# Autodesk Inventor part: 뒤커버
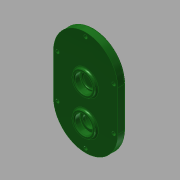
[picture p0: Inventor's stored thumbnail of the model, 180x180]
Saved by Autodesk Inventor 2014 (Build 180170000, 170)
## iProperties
Created: 2016-12
Part Number: 뒤커버
Material: 일반
Document SubType Name: Modeling
Designer: mduedu
Density: 1 g/cm^3
Appearance: 매끄러움 - 짙은 산림 녹색
Mass: 87.2434 g
Surface Area: 240.701 cm^2
Volume: 87.2434 cm^3
Author: mduedu
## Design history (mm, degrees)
sketch "스케치1"
  geometry: L1 (40, -25)-(40, 25); L2 (-40, 25)-(-40, -25); L3 (-40, -25)-(40, 25); L4 (40, -25)-(-40, 25); A1 r 40 centre (0, 25) between (40, 25) and (-40, 25); A2 r 40 centre (0, -25) between (-40, -25) and (40, -25); 1 further point
  constraints: 8 end point, 4 point on circle, 4 tangent, 2 centre point, 2 midpoint, 1 parallel, 1 vertical
  dimensions: "d0" = 130 dimension on A2 A1; "d2" = 80 distance between parallel lines of L1 L2
extrude "돌출1" new body sketch "스케치1" distance "d3" = 10; taper "d4" = 0 deg
sketch "스케치2"
  geometry: C1 r 14 at (0, 11); 1 further point
  constraints: 1 centre point, 1 vertical alignment
  dimensions: "d5" = 28 diameter of C1; "d6" = 11 distance of C1.centre point (0, 0)
extrude "돌출2" join sketch "스케치2" distance "d7" = 3; taper "d8" = 0 deg
sketch "스케치3"
  geometry: C1 r 14 at (0, -33.1); C2 r 14 at (0, 11) reference; 1 further point
  constraints: 1 centre point, 1 vertical alignment
  dimensions: "d9" = 28 diameter of C1; "d69" = 44.1 distance of C1.centre C2.centre
extrude "돌출3" join sketch "스케치3" distance "d11" = 3; taper "d12" = 0 deg
hole "구멍1" diameter "d15" = 22; stored, may be unused: countersink angle "d19" = 90 deg, drill point angle "d21" = 0 deg; dims "d13" = 10, "d14" = 10, "d16" = 6, "d17" = 4, "d18" = 2, "d20" = 7
hole "구멍2" diameter "d24" = 18; stored, may be unused: countersink angle "d28" = 90 deg, drill point angle "d30" = 0 deg; dims "d22" = 10, "d23" = 10, "d25" = 6, "d26" = 4, "d27" = 2, "d29" = 1
hole "구멍3" diameter "d33" = 22; stored, may be unused: countersink angle "d37" = 90 deg, drill point angle "d39" = 0 deg; dims "d31" = 10, "d32" = 10, "d34" = 6, "d35" = 4, "d36" = 2, "d38" = 7
sketch "스케치4"
  geometry: C1 r 14 at (0, -33.1) reference; C2 r 18 at (0, -33.1); 1 further point
  constraints: 1 centre point, 1 coincident
  dimensions: "d40" = 36 diameter of C2
extrude "돌출4" join sketch "스케치4" distance "d41" = 4; taper "d42" = 0 deg
hole "구멍4" diameter "d45" = 22; stored, may be unused: countersink angle "d49" = 90 deg, drill point angle "d51" = 0 deg; dims "d43" = 10, "d44" = 10, "d46" = 6, "d47" = 4, "d48" = 2, "d50" = 7
hole "구멍5" diameter "d54" = 15; stored, may be unused: countersink angle "d58" = 90 deg, drill point angle "d60" = 0 deg; dims "d52" = 10, "d53" = 10, "d55" = 6, "d56" = 4, "d57" = 2, "d59" = 7
fillet "모깎기1" dims "d61" = 0.3
fillet "모깎기2" dims "d62" = 2
chamfer "모따기1" distance "d63" = 1; stored, may be unused: second distance "d64" = 2, angle "d65" = 45 deg
fillet "모깎기3" dims "d66" = 2
fillet "모깎기4" dims "d67" = 2
fillet "모깎기5" dims "d68" = 2
sketch "스케치5"
  geometry: L1 (-40, 25)-(-40, -25) reference; L2 (40, -25)-(40, 25) reference; L3 (35, 25)-(35, -25); L4 (-35, -25)-(-35, 25); A1 r 40 centre (0, 25) between (40, 25) and (-40, 25) reference; A2 r 40 centre (0, -25) between (-40, -25) and (40, -25) reference; A3 r 35 centre (0, 25) between (35, 25) and (-35, 25); A4 r 35 centre (0, -25) between (-35, -25) and (35, -25); 2 further points
  constraints: 5 point on circle, 4 end point, 2 centre point, 1 vertical alignment, 3 other
  dimensions: "d70" = 5 distance between parallel lines of L2 L3
sketch "스케치6"
  geometry: 1 further point
hole "구멍6" sketch "스케치6" at (0, 60) diameter "d71" = 4.5; stored, may be unused: countersink angle "d75" = 90 deg, drill point angle "d77" = 0 deg; dims "d72" = 6, "d73" = 8, "d74" = 4.6, "d76" = 8
node "솔리드1"
pattern_linear "직사각형 패턴1"
